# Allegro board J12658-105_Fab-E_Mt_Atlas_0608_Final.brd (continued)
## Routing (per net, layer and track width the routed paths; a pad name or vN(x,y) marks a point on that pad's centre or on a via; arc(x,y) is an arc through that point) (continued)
VDD_HDR_EN: length 2.4
  TOP w0.127: v1(60.96,69.22) 60.67,69.5 U2.4
  BOTTOM w0.127: v1(60.96,69.22) 60.58,69.22 60.2,69.6 R131.2
VDD_HDR_FB: length 3.6
  TOP w0.127: R130.1 R132.2 R133.1 57.62,69.04 U2.3
VDD_IMU: length 15.1
  TOP w0.254: v1(28.59,49.64) 28.18,50.05 U14.8 ; U14.5 26.11,49.28 v1(25.59,48.77) ; R24.1 v1(22.29,51.82) 21.97,51.5 C14.1 21.46,51.43 FB6.2 ; R28.1 v1(22.29,50.8) 22.1,50.61 C15.1
  BOTTOM w0.508: v1(28.59,49.64) 26.47,49.64 v1(25.59,48.77) 24.32,48.77 v1(22.29,50.8) v1(22.29,51.82)
VDD_USB: length 40.4
  TOP w0.254: v1(16.32,61.4) U7.A1
  TOP w0.305: C8.1 17.08,60.64 v1(16.32,61.4)
  L3_SIG w0.508: v1(42.35,46.99) 42.35,48.52 38.17,52.71 38.17,60.17 v1(36.85,61.49)
  L4_SIG w0.381: v1(36.85,61.49) 36.63,61.49 36.04,62.08 25.5,62.08 25.32,61.9 18.08,61.9 18.06,61.93 16.84,61.93 v1(16.32,61.4)
  BOTTOM w0.381: R273.1 v1(42.35,46.99)
VDD_USB_EN: length 2.6
  TOP w0.254: U7.B2 18.1,63.18 C5.1
  TOP w0.508: R10.2 C5.1
VDD_USB_R: length 2.6
  BOTTOM w0.381: R273.2 C98.1 41.47,44.64 v1(41.41,44.58) 41.34,44.64 R33.1
15_4_GPIO0: length 8.1
  TOP w0.127: R97.1 v1(38.42,23.3) ; U29.10 40.95,18.28 v1(40.77,18.1)
  L3_SIG w0.127: v1(38.42,23.3) 38.42,21.97 39.94,20.45 39.94,18.92 v1(40.77,18.1)
15_4_GPIO1: length 7.9
  TOP w0.127: U29.9 41.04,18.78 v1(40.77,19.05) ; R83.2 R84.2 39.43,23.3 39.31,23.18 v1(39.31,22.23)
  L3_SIG w0.127: v1(39.31,22.23) 40.77,20.76 v1(40.77,19.05)
15_4_GPIO2: length 3.7
  TOP w0.127: R98.2 R99.2 41.72,21.02 42.48,21.02 42.82,20.68 U29.7
15_4_GPIO3: length 5.1
  TOP w0.127: R85.2 41.53,23.5 41.53,22.23 R100.2 42.61,21.72 43.32,21 U29.6
15_4_GPIO4: length 4.5
  TOP w0.127: R86.2 43.05,22.03 43.43,21.65 R101.2 43.82,21.53 U29.5
15_4_GPIO5: length 4.1
  TOP w0.127: R87.1 44.51,23.56 44.51,21.34 44.32,21.15 U29.4
15_4_RESET_N: length 67.4
  TOP w0.127: R108.1 v1(50.16,17.78)
  L3_SIG w0.127: v1(60.89,50.67) 60.89,50.32 60.63,50.06 60.63,48.82 61.27,48.18 61.27,33.46 60.69,32.88 60.69,31.26 60.77,31.18 60.77,17.88 v1(60.08,17.19)
  L4_SIG w0.127: v1(64.64,68.58) 64.33,68.26 64.33,66.55 61.53,63.75 61.53,51.31 v1(60.89,50.67) ; v1(60.08,17.19) 59.99,17.19 59.48,16.68 57.27,16.68 56.91,17.04 53.42,17.04 52.99,16.61 51.33,16.61 v1(50.16,17.78)
  BOTTOM w0.127: v1(64.64,68.58) 64.83,68.39 65.47,68.39 65.61,68.53 U32.3
15_4_RESET_N_R: length 1.8
  TOP w0.127: U29.25 R108.2
15_4_XIN: length 5.1
  TOP w0.127: C40.1 39.75,14.2 39.54,14.42 Y4.3 39.93,15 40.23,15 40.83,15.61 40.83,16.57 41.04,16.78 U29.13
15_4_XOUT: length 5.1
  TOP w0.127: U29.12 41.16,17.28 40.64,16.76 39.12,16.76 38.44,16.09 Y4.1 38.32,16.13 C37.1
A_3P3V: length 2.4
  TOP w0.508: FB10.2 10.29,33.15 10.16,33.02
A_5P0V: length 2.4
  TOP w0.508: 10.16,30.48 FB12.2
A_VIN: length 2.3
  TOP w0.508: FB13.2 10.16,22.86
ADC_AGND: length 1.5
  TOP w0.254: U22.L10 v1(37.38,43.57)
  BOTTOM w0.381: v1(37.38,43.57) 37.64,43.31 R192.1
AMBIENT_INT_N: length 2.2
  TOP w0.127: U10.4 19.79,56.52 v1(19.67,56.52)
  BOTTOM w0.127: v1(19.67,56.52) 20.32,55.87 R150.2
AP_COMP_AREF: length 13.5
  TOP w0.127: U22.H9 v1(34.98,42.77)
  BOTTOM w0.127: R170.2 R169.2 39.12,46.67 38.93,46.86 38.93,48.83 38.67,49.09 C75.1 R171.1 37.21,48.2 36.19,47.18 36.19,43.42 35.93,43.16 35.38,43.16 v1(34.98,42.77)
AP_GPIO0_ADC0_SPI_S_CS_N: length 73.4
  TOP w0.127: v1(30.99,45.3) 31.38,44.91 U22.D12
  L3_SIG w0.127: v1(7.75,46.48) 7.25,45.99 7.25,37.13 8.12,36.26 8.12,35.16 8.02,35.06 8.02,26.05 7.75,25.78 7.75,25.67 7.74,25.66 7.74,12.95 7.75,12.94 7.75,12.24 9.14,10.85 9.14,9.58 9.65,9.07 13.85,9.07 v1(14.67,8.25)
  L4_SIG w0.127: v1(30.99,45.3) 30.99,45.34 29.91,46.42 24.42,46.42 23.58,45.58 21.12,45.58 20.33,46.37 19.84,46.37 19.49,46.01 19.49,45.7 19.14,45.35 17.94,45.35 17.81,45.22 9,45.22 v1(7.75,46.48)
  BOTTOM w0.127: R178.2 29.46,46.61 29.84,46.23 30.06,46.23 v1(30.99,45.3) ; R258.2 v1(14.67,8.25)
AP_GPIO0_ADC0_SPI_S_CS_N_R_HDR: length 9.8
  BOTTOM w0.203: R258.1 12.38,8.25 11.75,7.62 11.75,6.86 11.05,6.16 9.21,6.16 8.13,5.08 5.08,5.08
AP_GPIO1_ADC1_SPI_S_MISO: length 111.7
  TOP w0.127: U28.13 26.11,21.66 v1(24.96,20.51) ; U22.E10 v1(31.78,43.57)
  L3_SIG w0.127: v1(11.18,43.05) 11.85,42.37 11.85,41.49 11.75,41.39 11.75,38.77 11.85,38.67 11.85,38.42 11.9,38.37 11.9,37.44 11.91,37.43 11.91,37.04 11.91,36.67 11.91,36.67 11.91,36.63 12.08,36.47 12.08,16.12 v1(14.61,13.59) ; v1(27.05,31.81) 27.05,30.71 24.93,28.59 24.53,28.59 23.23,27.28 23.23,25.35 24,24.57 24,22.86 24.96,21.91 v1(24.96,20.51)
  L4_SIG w0.127: v1(11.18,43.05) 12.44,43.05 13.4,44.01 17.01,44.01 17.69,43.32 18.88,43.32 19.18,43.02 21.05,43.02 21.34,43.31 21.46,43.31 22.03,43.88 27.24,43.88 27.95,43.17 31.26,43.17 31.65,43.57 v1(31.78,43.57) ; v1(41.71,34.06) 41.55,33.91 40.46,33.91 39.34,32.79 30.96,32.79 30.39,33.36 27.72,33.36 27.05,32.69 27.05,32.36 27.05,32.36 v1(27.05,31.81) ; v1(24.96,20.51) 18.86,20.51 18.66,20.31 17.92,20.31 17.27,20.96 16.19,20.96 15.94,20.7 14.29,20.7 13.91,20.32 13.91,14.29 v1(14.61,13.59)
  BOTTOM w0.127: R213.2 40.83,38.16 40.83,35.57 41.71,34.69 v1(41.71,34.06) ; R242.2 v1(14.61,13.59)
AP_GPIO1_ADC1_SPI_S_MISO_HDR: length 9.6
  BOTTOM w0.203: J15.38 7.56,10.16 8.81,11.42 10.66,11.42 12.3,13.06 12.3,13.44 12.45,13.59 R242.1
AP_GPIO2_ADC2_SPI_S_SCK: length 51.7
  TOP w0.127: U22.E11 v1(31.78,44.37)
  L3_SIG w0.127: v1(14.61,16.26) 12.53,18.33 12.53,36.66 12.37,36.82 12.37,36.85 12.37,37.62 12.36,37.63 12.36,38.56 12.36,38.56 12.31,38.61 12.31,38.86 12.2,38.96 12.2,41.2 12.31,41.3 12.31,43.95 v1(12.19,44.07)
  L4_SIG w0.127: v1(31.78,44.37) 31.38,44.77 30.82,44.77 30.59,45 30.59,45.32 29.72,46.19 24.51,46.19 23.67,45.35 20.42,45.35 19.86,44.79 19.53,44.79 19.07,44.34 18.17,44.34 17.93,44.58 12.7,44.58 v1(12.19,44.07)
  BOTTOM w0.127: R236.2 v1(14.61,16.26)
AP_GPIO2_ADC2_SPI_S_SCK_HDR: length 9.5
  BOTTOM w0.203: R236.1 12.49,16.26 10.26,14.03 9.58,14.03 8.25,12.7 J15.36
AP_GPIO3_ADC3_SPI_S_MOSI: length 63.5
  TOP w0.127: U22.E12 v1(31.78,45.17)
  L3_SIG w0.127: v1(10.16,45.85) 10.16,43.94 8.81,42.6 8.81,37.54 8.81,37.33 9.27,36.88 9.27,35.03 9.27,34.84 9.26,34.83 9.26,34.68 9.16,34.59 9.16,26.87 9.44,26.59 10.86,26.59 11.16,26.29 11.16,13.56 13.8,10.92 v1(14.61,10.92)
  L4_SIG w0.127: v1(31.78,45.17) 30.53,46.42 30.3,46.65 24.32,46.65 24.04,46.37 20.65,46.37 20.42,46.6 19.74,46.6 19.26,46.11 19.26,46 18.83,45.58 12.36,45.58 12.09,45.85 v1(10.16,45.85)
  BOTTOM w0.127: R251.2 v1(14.61,10.92)
AP_GPIO3_ADC3_SPI_S_MOSI_HDR: length 9.4
  BOTTOM w0.203: R251.1 12.76,10.6 12.45,10.6 10.73,8.89 9.78,8.89 8.51,7.62 J15.40
AP_GPIO4_ADC4: length 72.8
  TOP w0.127: v1(38.42,25.65) R83.1 ; 54.9,46.13 54.99,46.23 R38.1 ; 54.9,46.13 v1(54.86,46.13) ; 54.9,46.13 54.15,45.38 54.15,43.93 53.55,43.33 53.55,42.25 53.09,41.79 v1(53.09,41.27) ; U22.F9 v1(32.58,42.77)
  L3_SIG w0.127: v1(54.86,46.13) 55.66,46.13 56.31,45.48 56.31,39.57 56.44,39.44 56.44,25.14 v1(57.19,24.39)
  L4_SIG w0.127: v1(57.19,24.39) 54.22,24.39 53.4,25.21 42.72,25.21 42.13,25.8 40.49,25.8 39.95,25.26 38.81,25.26 v1(38.42,25.65) ; v1(32.58,42.77) 32.98,43.16 34.35,43.16 34.58,42.93 34.58,42.62 34.83,42.36 36.75,42.36 36.99,42.12 36.99,41.8 37.22,41.57 39.28,41.57 40.2,40.65 52.46,40.65 v1(53.09,41.27)
AP_GPIO4_ADC4_HDR: length 8
  TOP w0.203: J14.13 61.34,48.26 59.31,46.23 R38.2
AP_GPIO5_ADC5: length 73.2
  TOP w0.127: v1(54.74,43.18) R44.1 ; v1(32.58,43.57) 32.98,43.17 U22.F10 ; R98.1 v1(40.01,23.37)
  L3_SIG w0.127: v1(60.25,29.06) 60.55,29.35 60.55,31.09 60.46,31.17 60.46,32.98 60.63,33.14 60.9,33.41 60.9,37.64 60.93,37.68 60.93,42.88 v1(60.63,43.18) ; v1(40.01,23.37) v1(40.01,28.6)
  L4_SIG w0.127: v1(60.25,29.06) 59.75,28.56 52.01,28.56 51.75,28.31 50.89,28.31 50.13,29.07 45.47,29.07 45.34,29.2 42.53,29.2 41.89,28.56 40.65,28.56 40.61,28.6 v1(40.01,28.6) ; v1(32.58,43.57) 32.98,43.96 34.35,43.96 34.59,43.72 34.59,43.4 34.82,43.17 38.72,43.17 39.78,44.23 40.72,44.23 41.04,43.92 44.92,43.92 45.16,43.68 49.07,43.68 49.28,43.88 49.72,43.88 50.81,42.79 54.34,42.79 v1(54.74,43.18) v1(60.63,43.18)
AP_GPIO5_ADC5_HDR: length 8.2
  TOP w0.203: J14.15 61.28,45.72 59.18,43.62 57.59,43.62 57.15,43.18 R44.2
AP_GPIO6_ADC6: length 15
  TOP w0.127: v1(33.71,31.06) 33.18,31.59 U38.4 ; U22.L9 v1(37.38,42.77)
  L3_SIG w0.127: v1(33.71,31.06) 33.84,31.2 33.84,34.62 34.24,35.02 34.24,35.38 35.62,36.76 35.93,36.76 36.18,37.01 36.18,40.69 36.98,41.49 36.98,42.36 v1(37.38,42.77)
AP_GPIO6_ADC6_HDR: length 8
  TOP w0.203: R47.2 61.47,41.15 J14.17
AP_GPIO6_ADC6_MUX: length 54
  TOP w0.127: v1(54.67,41.85) 54.67,41.5 55.03,41.15 R47.1 ; U38.1 31,32.89 31.37,32.52 31.37,31.62 v1(31.94,31.05) ; v1(41.76,25.41) 41.25,24.89 R85.1
  L3_SIG w0.127: v1(54.74,23.88) 55.36,24.5 55.36,35.14 54.99,35.51 54.54,35.51 54.26,35.79 54.26,36.4 55.23,37.38 55.23,40.9 54.67,41.46 v1(54.67,41.85) ; v1(31.86,26.04) 31.86,29.52 32.09,29.74 32.09,30.9 v1(31.94,31.05)
  L4_SIG w0.127: v1(31.86,26.04) 32.36,26.53 34.59,26.53 36.09,25.03 40.05,25.03 40.42,25.41 v1(41.76,25.41) 42.21,24.96 53.02,24.96 54.1,23.88 v1(54.74,23.88)
AP_GPIO7_ADC7: length 76.3
  TOP w0.127: R261.1 v1(57.66,2.54) ; U22.K8 v1(36.58,41.97)
  L3_SIG w0.127: v1(57.66,2.54) 57.36,2.84 57.36,23.01 57.47,23.11 57.47,23.7 58.06,24.3 58.06,24.89 57.92,25.02 57.08,25.86 57.08,37.47 57.71,38.09 57.71,38.5 56.54,39.67 56.54,46.51 56.67,46.64 56.67,49 v1(56.52,49.15)
  L4_SIG w0.127: v1(56.52,49.15) 56.06,48.69 53.62,48.69 53.34,48.41 47.85,48.41 47.2,47.76 44.04,47.76 43.22,48.59 41.61,48.59 v1(41.27,48.26)
  BOTTOM w0.127: v1(41.27,48.26) 40.96,47.94 40.96,46.29 40.78,46.12 40.46,46.12 39.69,45.34 R33.2 39.31,44.64 38.64,43.97 37.23,43.97 36.98,43.72 36.98,42.36 v1(36.58,41.97) 36.64,41.91 R199.1
AP_GPIO7_ADC7_HDR: length 5
  TOP w0.203: 63.5,5.08 60.96,2.54 R261.2
AP_GPIO8_SPI1_M_SCK: length 78.7
  TOP w0.127: U22.D6 31.38,39.97 v1(30.98,39.57) ; R96.1 49.91,22.23 v1(50.23,21.91) ; R63.2 v1(13.91,34.42)
  L3_SIG w0.127: v1(14.49,37.8) 14.69,37.6 14.69,35.84 14.64,35.79 14.64,35.15 v1(13.91,34.42) 13.91,30.28 14.48,29.71 14.48,27.91 14.28,27.71 13.64,27.71 13.45,27.52 13.45,26.81 13.62,26.64 13.99,26.64 14.33,26.31 14.33,23.02 v1(13.84,22.54)
  L4_SIG w0.127: v1(13.84,22.54) 14.14,22.84 23.52,22.84 23.75,22.61 32.31,22.61 v1(33.36,21.55) 33.62,21.81 38.76,21.81 39.12,21.45 44.94,21.45 45.08,21.58 45.59,22.1 50.04,22.1 v1(50.23,21.91) ; v1(14.49,37.8) 14.93,38.24 23.17,38.24 23.69,37.72 24.57,37.72 25.4,38.56 26.34,38.56 26.63,38.85 29.55,38.85 29.86,39.16 30.58,39.16 v1(30.98,39.57)
  BOTTOM w0.127: R229.2 31.88,19.16 32.55,19.84 32.91,19.84 33.36,20.29 v1(33.36,21.55)
AP_GPIO8_SPI1_M_SCK_BLE: length 2.7
  TOP w0.127: U30.12 31.71,16.22 31.88,16.38 v1(31.88,17.14)
  BOTTOM w0.127: R229.1 v1(31.88,17.14)
AP_GPIO8_SPI1_M_SCK_HDR: length 7.9
  TOP w0.203: J15.20 6.57,34.51 10.92,34.51 11.01,34.42 R63.1
AP_GPIO8_SPI1_M_SCK_R: length 4.3
  TOP w0.127: R96.2 48.13,22.23 47.62,21.72 47.62,19.56 47.35,19.28 U29.28
AP_GPIO9_SPI1_M_MISO: length 78.4
  TOP w0.127: v1(29.38,39.57) 29.78,39.97 U22.B6 ; R73.2 v1(13.84,29.21) ; R92.1 v1(49.15,25.65)
  L3_SIG w0.127: v1(47.12,20.37) 48.77,22.02 48.77,25.27 v1(49.15,25.65) ; v1(21.27,29.66) 21.02,29.42 21.02,28.02 20.69,27.69 20.69,22.39 v1(21.32,21.76) ; v1(13.84,29.21) 13.51,29.54 13.51,34.58 13.94,35.01 14,35.01 14.41,35.43 14.41,35.88 14.47,35.93 14.47,36.93 v1(13.91,37.48)
  L4_SIG w0.127: v1(29.38,39.57) 28.89,39.08 26.54,39.08 26.24,38.79 22.11,38.79 21.8,38.47 14.6,38.47 13.91,37.78 v1(13.91,37.48) ; v1(13.84,29.21) 14.49,29.86 21.07,29.86 v1(21.27,29.66) ; v1(21.32,21.76) 22.78,21.76 23.58,20.97 24.52,20.97 25.39,21.84 28.24,21.84 29.25,20.83 30.52,20.83 31.17,20.18 32.02,20.18 v1(32.77,19.43) 32.96,19.62 33.88,19.62 33.88,19.63 38.51,19.63 39.26,20.37 v1(47.12,20.37)
  BOTTOM w0.127: v1(32.77,19.43) R228.2
AP_GPIO9_SPI1_M_MISO_BLE: length 3.8
  TOP w0.127: U30.11 31.65,15.52 32.77,16.64 v1(32.77,17.14)
  BOTTOM w0.127: R228.1 v1(32.77,17.14)
AP_GPIO9_SPI1_M_MISO_HDR: length 7.8
  TOP w0.203: R73.1 11.62,29.21 11.37,29.46 6.1,29.46 J15.22
AP_GPIO9_SPI1_M_MISO_R: length 6.4
  TOP w0.127: U29.1 45.82,20.87 45.97,21.02 46.99,21.02 47.28,21.3 47.28,22.32 48.13,23.18 R91.1 R92.2
AP_GPIO10_SPI1_M_MOSI: length 77.6
  TOP w0.127: v1(28.58,39.57) 28.98,39.97 U22.A6 ; R90.1 v1(47.12,25.65) ; R77.2 v1(13.84,27.18)
  L3_SIG w0.127: v1(47.12,25.65) 47.12,21.91 v1(46.8,21.59) ; v1(15.75,21.15) 15.62,21.27 15.62,25.4 v1(13.84,27.18) 14.06,27.18 14.7,27.82 14.7,30.37 14.34,30.73 14.34,33.31 14.94,33.91 15.29,33.91 15.63,34.25 15.63,34.66 15.1,35.19 15.1,35.6 15.15,35.65 15.15,38.03 14.86,38.32 14.86,38.87 v1(14.65,39.08)
  L4_SIG w0.127: v1(46.8,21.59) 45.4,21.59 45.3,21.49 45.3,21.49 45.04,21.22 39.03,21.22 38.67,21.58 34.79,21.58 v1(34.42,21.21) 34.02,20.82 31.83,20.82 31.62,21.02 31.16,21.02 30.11,22.06 25.49,22.06 25.3,22.06 24.43,21.2 23.67,21.2 22.71,22.16 16.76,22.16 v1(15.75,21.15) ; v1(14.65,39.08) 14.95,39.38 19.74,39.38 20.35,38.77 21.77,38.77 22.16,39.15 25.09,39.15 25.58,39.64 26.2,39.64 26.27,39.57 v1(28.58,39.57)
  BOTTOM w0.127: R245.2 33.59,19.48 34.42,20.3 v1(34.42,21.21)
AP_GPIO10_SPI1_M_MOSI_BLE: length 9.3
  TOP w0.127: U30.8 31.79,13.42 32.13,13.08 32.13,12.45 v1(32.64,11.94)
  BOTTOM w0.127: R245.1 33.59,12.89 v1(32.64,11.94)
AP_GPIO10_SPI1_M_MOSI_HDR: length 7.7
  TOP w0.203: J15.24 6.03,26.99 11.11,26.99 11.3,27.18 R77.1
AP_GPIO10_SPI1_M_MOSI_R: length 4.6
  TOP w0.127: R90.2 47.12,22.8 45.32,21 U29.2
AP_GPIO11_SPI1_M_CS0_N: length 93.9
  TOP w0.127: U22.C6 30.58,39.97 v1(30.18,39.57) ; R81.2 v1(13.84,25.15) ; R89.1 v1(46.1,25.65)
  L3_SIG w0.127: v1(8.64,25.27) 8.8,25.44 8.8,26.58 8.7,26.68 8.7,34.78 8.8,34.87 8.8,36.66 8.33,37.13 8.33,41.9 v1(8,42.23) ; v1(46.09,23.31) 46.1,23.32 v1(46.1,25.65)
  L4_SIG w0.127: v1(30.18,39.57) 29.79,39.96 27.82,39.96 27.73,39.87 25.34,39.87 24.96,39.48 22.77,39.48 21.98,40.27 21.34,40.27 21.11,40.5 14.81,40.5 14.24,41.07 11.19,41.07 10.61,41.65 8.58,41.65 v1(8,42.23) ; v1(46.09,23.31) 45.51,23.31 45.04,22.85 41.94,22.85 41.5,23.28 41.5,23.38 41.18,23.7 40.86,23.7 40.4,23.24 40.4,23.2 40.17,22.97 39.84,22.97 39.61,23.2 38.87,23.2 38.52,22.85 34.75,22.85 33.83,23.76 27.18,23.76 25.94,25 24.16,25 23.83,25.34 22.08,25.34 22.07,25.35 21.74,25.35 20.91,24.51 19.1,24.51 18.13,25.48 17.81,25.48 17.58,25.25 17.58,24.88 17.45,24.75 14.24,24.75 v1(13.84,25.15) 12.39,26.6 9.42,26.6 8.64,25.82 v1(8.64,25.27)
  BOTTOM w0.127: R211.2 29.02,34.65 29.79,35.42 29.79,39.17 v1(30.18,39.57)
AP_GPIO11_SPI1_M_CS0_N_HDR: length 7.9
  TOP w0.203: R81.1 11.68,25.15 11.01,24.47 8.29,24.47 7.37,25.4 J15.26
AP_GPIO11_SPI1_M_CS0_N_R: length 4.9
  TOP w0.127: R89.2 R88.2 45.09,22.23 44.82,21.96 U29.3
AP_GPIO12_SPI1_M_CS1_N: length 55.7
  TOP w0.127: U22.B5 29.35,38.73 27.28,38.73 v1(26.8,38.25) ; R263.1 v1(16.28,11.49)
  L3_SIG w0.127: v1(22.23,27.05) 22.23,27.27 22.52,27.56 22.52,27.84 24.3,29.61 24.3,31.1 26.04,32.84 26.04,34.11 25.57,34.58 25.57,37.24 25.81,37.48 26.02,37.48 v1(26.8,38.25) ; v1(17.14,25.15) 17.14,24.32 17.01,24.18 17.01,20.19 16.13,19.31 16.13,18.38 15.52,17.78 15.52,12.25 v1(16.28,11.49)
  L4_SIG w0.127: v1(29.21,11.05) 28.37,11.89 16.67,11.89 v1(16.28,11.49) ; v1(17.14,25.15) 19.05,27.05 v1(22.23,27.05)
  BOTTOM w0.127: R250.2 v1(29.21,11.05) ; R216.2 v1(17.14,25.15) ; v1(26.8,38.25) 26.9,38.25 R205.2
AP_GPIO12_SPI1_M_CS1_N_BLE: length 3.9
  TOP w0.127: v1(32.64,11.05) 31.88,11.81 31.88,12.57 31.73,12.72 U30.7
  BOTTOM w0.127: R250.1 v1(32.64,11.05)
AP_GPIO12_SPI1_M_CS1_N_HDR: length 11
  BOTTOM w0.203: R216.1 14.61,24.64 13.43,24.64 12.92,24.13 9.65,24.13 8.38,22.86 J15.28
AP_GPIO13_SPI1_M_CS2_N: length 47.8
  TOP w0.127: v1(32.95,34.23) 27.67,34.23 26.54,35.36 26.54,37.28 v1(25.75,38.08) 26.84,39.17 U22.A5
  L3_SIG w0.127: v1(32.95,34.23) 32.54,33.82 32.54,33.43 32.54,33.42 32.54,33.37 32.77,33.14 32.79,33.14 32.8,33.13 32.8,30.29 32.79,30.28 32.79,29.96 32.8,29.95 32.8,25.14 32.51,24.84 32.51,20.57 31.83,19.89 v1(31.83,19.75)
  L4_SIG w0.127: v1(18.16,20.76) 18.19,20.74 24.62,20.74 25.42,21.54 28.21,21.54 29.25,20.5 30.44,20.5 31.19,19.75 v1(31.83,19.75)
  BOTTOM w0.127: R214.1 34.73,34.09 34.59,34.23 v1(32.95,34.23) ; R206.2 26.12,38.08 v1(25.75,38.08) ; 18.16,21.59 v1(18.16,20.76)
AP_GPIO13_SPI1_M_CS2_N_HDR: length 13.1
  BOTTOM w0.203: R219.1 17.14,21.59 16.66,22.07 11.72,22.07 10.78,21.13 8.36,21.13 7.56,20.32 J15.30
AP_GPIO14_SPI1_M_CS3_N: length 94.7
  TOP w0.127: v1(30.98,38.77) 31.38,39.17 U22.D5
  L3_SIG w0.127: v1(24.26,19.18) 25.35,20.27 25.35,22.14 24.24,23.25 24.24,24.85 23.46,25.63 23.46,27.19 24.63,28.36 25.02,28.36 27.65,30.98 27.65,31.2 27.83,31.38 27.83,32.74 27.06,33.51 27.06,35.75 27.04,35.78 27.04,36.11 27.96,37.03 27.96,37.44 28.19,37.67 28.19,38.13 28.42,38.36 30.58,38.36 v1(30.98,38.77) 31.23,38.77 31.62,39.17 31.99,39.17 32.18,39.35 32.18,39.73 31.39,40.52 31.39,41.32 31.14,41.57 30.83,41.57 30.58,41.81 30.58,42.12 30.34,42.37 28.82,42.37 26.61,44.58 26.61,45.51 25.09,47.02 24.69,47.02 23.88,47.83 23.88,50.93 23.73,51.09 23.73,52.8 25.42,54.49 25.42,62.59 v1(26.2,63.37)
  L4_SIG w0.127: v1(14.67,20.26) 15.37,19.56 15.75,19.56 16.38,18.92 19.81,18.92 20.32,18.41 23.5,18.41 v1(24.26,19.18) ; v1(26.2,63.37) 27.84,63.37 29.62,65.15 39.87,65.15 v1(40.83,66.1)
  BOTTOM w0.127: v1(14.67,20.26) 14.22,20.7 R222.2 ; C104.1 v1(40.83,66.1) 40.83,66.11 40.83,67.73 40.83,67.74 40.83,68.83 41.08,69.09 R135.2 ; v1(30.98,38.77) 30.59,38.37 30.59,34.72 R210.2
AP_GPIO14_SPI1_M_CS3_N_HDR: length 9.7
  BOTTOM w0.203: R222.1 11.94,20.7 10.99,19.75 8.95,19.75 8.06,18.86 8.06,18.1 7.75,17.78 J15.32
AP_GPIO15_I2S_RXD: length 46.9
  TOP w0.127: U22.C5 30.58,39.17 v1(30.18,38.77) ; U25.3 32.85,30.06 32.96,30.16 33.15,30.16 33.19,30.12 v1(33.19,30.12) ; v1(54.74,33.02) R67.2
  L3_SIG w0.127: v1(25.79,30.14) 25.79,31.11 26.82,32.14 26.82,35.68 26.81,35.68 26.81,36.21 27.13,36.52 27.13,36.93 27.96,37.76 27.96,38.23 28.5,38.77 v1(30.18,38.77)
  L4_SIG w0.127: v1(54.74,33.02) 54.34,32.63 51.14,32.63 50.06,33.71 48.81,33.71 48.18,33.08 46.04,33.08 45.9,32.94 40.78,32.94 39.89,32.05 33.58,32.05 33.19,31.67 33.19,30.12 ; 33.19,30.12 33.15,30.16 32.51,30.16 32.07,30.61 31.53,30.61 30.88,29.96 25.97,29.96 v1(25.79,30.14) ; 33.19,30.12 v1(33.19,30.12)
AP_GPIO15_I2S_RXD_HDR: length 12.6
  TOP w0.203: J14.28 64.77,31.75 64.77,33.4 64.08,34.09 62.6,34.09 61.59,33.08 56.45,33.08 R67.1
AP_GPIO16_I2S_RSCK: length 52.9
  TOP w0.127: U22.B4 29.78,38.37 v1(29.38,37.97) ; R80.2 54.74,26.67 v1(54.74,26.92) ; v1(24.75,26.67) 26.1,26.67 26.76,27.32 U28.3
  L3_SIG w0.127: v1(29.38,37.97) 28.99,37.57 28.99,34.78 28.75,34.55 28.75,30.67 26.44,28.36 25.97,28.36 25.51,27.9 25.18,27.9 24.75,27.47 v1(24.75,26.67)
  L4_SIG w0.127: v1(54.74,26.92) 54.1,27.56 54.1,28.07 53.83,28.33 52.1,28.33 51.85,28.08 50.79,28.08 50.03,28.84 45.38,28.84 45.25,28.97 42.62,28.97 41.86,28.21 39.84,28.21 38.89,29.16 34.92,29.16 34.68,28.92 26.2,28.92 24.75,27.47 v1(24.75,26.67)
AP_GPIO16_I2S_RSCK_HDR: length 10.8
  TOP w0.203: J14.30 64.75,26.65 62.79,26.65 61.69,25.55 56.75,25.55 R80.1
AP_GPIO17_I2S_RWS: length 44.3
  TOP w0.127: v1(30.23,25.91) 30.84,26.52 30.84,27.53 30.9,27.6 U25.6 ; v1(30.98,37.97) 31.38,38.37 U22.D4 ; v1(54.74,24.89) 54.74,24.64 R94.2
  L3_SIG w0.127: v1(30.98,37.97) 31.38,37.57 31.38,37.01 31.63,36.77 31.95,36.77 32.18,36.53 32.18,35.36 31.52,34.7 31.52,30.55 31.34,30.37 31.34,30.33 30.77,29.76 30.77,26.46 v1(30.23,25.91)
  L4_SIG w0.127: v1(30.23,25.91) 30.66,26.34 31.52,26.34 32.01,26.83 34.62,26.83 35.35,26.1 51.67,26.1 51.69,26.07 53.12,26.07 54.3,24.89 v1(54.74,24.89)
AP_GPIO17_I2S_RWS_HDR: length 10.3
  TOP w0.203: J14.32 64.77,24.13 61.59,24.13 61.34,23.88 R94.1
AP_GPIO18_I2S_TSCK: length 51.3
  TOP w0.127: U22.A4 28.98,38.37 v1(28.58,37.97) ; U28.6 24.81,27.6 24.74,27.53 24.74,27.27 24.13,26.66 v1(24.13,25.91)
  L3_SIG w0.127: v1(24.13,25.91) 24.13,26.7 24.52,27.09 24.52,27.56 25.09,28.13 25.42,28.13 25.88,28.59 26.36,28.59 28.52,30.76 28.52,33.22 28.19,33.55 28.19,37.35 28.58,37.74 v1(28.58,37.97)
  L4_SIG w0.127: v1(24.13,25.91) 24.52,25.51 25.34,25.51 26.13,26.3 27.34,26.3 27.65,26 27.65,25.9 28.08,25.46 29.64,25.46 29.91,25.2 31.49,25.2 31.51,25.19 32.22,25.19 32.23,25.2 33.73,25.2 33.87,25.06 35.1,25.06 35.81,24.35 40.33,24.35 40.37,24.38 41.81,24.38 41.93,24.27 51.85,24.27 53.21,22.91 v1(53.21,22.86)
  BOTTOM w0.127: R218.2 54.04,22.1 53.27,22.86 v1(53.21,22.86)
AP_GPIO18_I2S_TSCK_HDR: length 11.2
  BOTTOM w0.203: 66.04,22.86 64.9,21.72 62.57,21.72 62.56,21.73 57.58,21.73 57.21,22.1 R218.1
AP_GPIO19_I2S_TWS: length 61.9
  TOP w0.127: U22.C4 30.58,38.37 v1(30.18,37.97) ; v1(21.91,24.96) 23.69,24.96 24.16,24.49 U28.10
  L3_SIG w0.127: v1(21.91,24.96) 21.6,25.26 21.6,27.31 22.06,27.77 22.06,28.03 22.68,28.65 22.68,30.74 23.84,31.89 23.84,36.41 v1(24.26,36.83)
  L4_SIG w0.127: v1(53.79,19.51) 54.09,19.51 54.55,19.96 54.55,20.6 53.74,21.4 51.15,21.4 50.88,21.67 50.88,21.95 50.88,22.14 50.87,22.15 50.86,22.15 50.85,22.16 50.85,22.17 50.49,22.53 50.48,22.53 50.44,22.58 45.42,22.58 45.23,22.39 39.78,22.39 39.42,22.74 39.06,22.74 38.71,22.39 34.56,22.39 33.74,23.21 25.43,23.21 23.69,24.96 v1(21.91,24.96) ; v1(30.18,37.97) 29.79,38.36 27.82,38.36 27.17,37.71 25.93,37.71 25.06,36.83 v1(24.26,36.83)
  BOTTOM w0.127: v1(53.79,19.51) 53.8,19.49 R224.2
AP_GPIO19_I2S_TWS_HDR: length 11.2
  BOTTOM w0.203: 66.04,20.32 64.85,19.13 63.11,19.13 62.93,19.3 57.66,19.3 57.43,19.53 55.54,19.53 R224.1
AP_GPIO20_I2S_TXD: length 55
  TOP w0.127: v1(29.39,37.17) 29.78,37.57 U22.B3 ; U25.10 30.25,24.49 v1(30.23,24.51)
  L3_SIG w0.127: v1(30.23,24.51) 30.23,17.91 v1(30.99,17.14) ; v1(29.39,37.17) 29.78,36.78 29.78,33.3 29.97,33.11 29.97,30.9 26.64,27.56 26.64,26.86 26.16,26.39 v1(26.16,25.78)
  L4_SIG w0.127: v1(30.99,17.14) 31.48,16.65 33.42,16.65 34.25,17.49 34.9,17.49 35.17,17.76 37.42,17.76 37.78,17.4 37.78,16.64 39.13,15.29 48.84,15.29 48.97,15.16 53.07,15.16 v1(53.53,15.62) ; v1(30.23,24.51) 29.84,24.51 29.4,24.96 26.99,24.96 v1(26.16,25.78)
  BOTTOM w0.114: R233.2 54.13,17.4 53.53,16.8 v1(53.53,15.62)
AP_GPIO20_I2S_TXD_HDR: length 11.3
  BOTTOM w0.203: 66.04,17.78 64.9,16.64 57.79,16.64 57.02,17.4 R233.1
AP_GPIO21_SPI0_M_SCK: length 46.3
  TOP w0.127: U22.A3 28.98,37.57 v1(28.59,37.17) ; v1(10.1,52.93) 9.49,52.93 R20.2 ; U23.13 22.16,33.73 21.71,33.27 21.08,33.27 19.98,34.37 v1(19.98,34.81) ; U15.6 v1(19.18,49.98)
  L3_SIG w0.127: v1(19.98,34.81) 19.83,34.96 19.83,36.14 20.07,36.37 v1(20.07,36.83) 20.07,38.28 20.04,38.31 20.04,38.78 20,38.82 20,39.6 19.98,39.62 19.68,39.92 19.68,42.73 20.26,43.31 20.26,43.82 20.26,43.82 20.26,44.77 19.61,45.42 19.61,47.17 20.11,47.67 20.11,48.11 20.2,48.2 20.2,48.56 19.18,49.58 v1(19.18,49.98)
  L4_SIG w0.127: v1(28.59,37.17) 26.62,37.17 25.88,36.44 23.81,36.44 23.42,36.83 v1(20.07,36.83) ; v1(19.18,49.98) 18.43,50.72 16.26,50.72 14.86,49.33 14.26,49.33 13.99,49.59 9.78,49.59 9.35,50.03 9.35,52.21 10.1,52.96 v1(10.1,52.93)
AP_GPIO21_SPI0_M_SCK_HDR: length 3.5
  TOP w0.203: R20.1 8.19,53.34 J15.4
AP_GPIO22_SPI0_M_MISO: length 50.2
  TOP w0.127: U22.C3 30.58,37.57 v1(30.18,37.17) ; U15.2 v1(14.6,50.48) ; v1(20.46,31.59) 21.3,31.59 21.49,31.78 U23.10 24.05,31.78 24.25,31.98 24.25,32.22 24.49,32.46 24.56,32.46 24.73,32.63 24.73,33.43 v1(24.38,33.78) ; R27.2 10.22,50.8 v1(10.86,50.16)
  L3_SIG w0.127: v1(22.21,50) 22.21,45.15 21.5,44.44 21.4,44.44 21.01,44.05 21.01,43.09 20.74,42.82 20.74,38.58 20.94,38.38 20.94,35.22 20.71,34.99 20.71,34.49 20.39,34.17 20.39,31.66 v1(20.46,31.59) ; v1(24.26,36.03) 24.38,35.9 v1(24.38,33.78)
  L4_SIG w0.127: v1(24.26,36.03) 25.8,36.03 26.37,36.6 28.57,36.6 28.99,37.02 28.99,37.33 29.22,37.57 29.79,37.57 v1(30.18,37.17) ; v1(10.86,50.16) 10.99,50.29 12.83,50.29 13.01,50.48 v1(14.61,50.48) 15.26,51.13 21.09,51.13 v1(22.21,50)
AP_GPIO22_SPI0_M_MISO_HDR: length 3.4
  TOP w0.203: R27.1 J15.6
AP_GPIO23_SPI0_M_MOSI: length 55.3
  TOP w0.127: v1(30.98,37.17) 31.38,37.57 U22.D3 ; U23.6 18.26,32.43 18.32,32.36 18.63,32.36 19.91,31.08 v1(19.91,30.7) ; v1(19.72,48.29) 18.53,49.48 U15.5 ; v1(10.16,48.13) R35.2
  L3_SIG w0.127: v1(19.91,30.7) 19.36,31.25 19.36,37.23 19.52,37.39 19.52,39.15 19.23,39.45 19.23,44.34 19.38,44.5 19.38,47.95 v1(19.72,48.29)
  L4_SIG w0.127: v1(31.69,30.15) 31.27,29.73 24.13,29.73 23.69,29.29 22.66,29.29 21.85,30.1 20.52,30.1 v1(19.91,30.7) ; v1(19.72,48.29) 19.61,48.4 15.33,48.4 14.77,47.84 10.46,47.84 v1(10.16,48.13)
  BOTTOM w0.127: v1(30.98,37.17) 31.38,36.77 31.38,35.16 31.28,35.05 31.28,34.71 31.38,34.61 31.38,30.87 31.69,30.56 v1(31.69,30.15)
AP_GPIO23_SPI0_M_MOSI_HDR: length 3.4
  TOP w0.203: J15.8 5.21,48.13 R35.1
AP_GPIO24_SPI0_M_CS0_N: length 52.5
  TOP w0.127: v1(10.79,46.48) 9.97,46.48 R39.2 ; U15.1 14.81,50.98 14.61,51.18 v1(14.61,51.75) ; U22.E4 32.18,38.37 v1(31.78,37.97)
  L3_SIG w0.127: v1(20.43,52.33) 20.72,52.04 20.72,48.4 20.44,48.11 20.44,47.44 20.49,47.39 20.49,43.22 19.98,42.71 19.98,39.94 20.23,39.69 20.23,38.92 20.27,38.88 20.27,38.4 20.49,38.19 20.49,36.12 v1(20.25,35.88) ; v1(10.79,46.48) 9.91,46.48 8.83,47.56 8.83,48.89 v1(10.1,50.16)
  L4_SIG w0.127: v1(10.1,50.16) 11.68,51.75 v1(14.61,51.75) 16,51.75 16.44,52.19 17.76,52.19 17.97,51.98 18.53,51.98 18.88,52.33 v1(20.43,52.33) ; v1(20.25,35.88) 20.8,36.44 22.61,36.44 23.62,35.43 23.75,35.3 24.77,35.3 25.02,35.55 27.63,35.55 28.33,36.25 29.21,36.25 29.74,36.77 30.35,36.77 30.58,37.01 30.58,37.32 30.83,37.57 31.31,37.57 31.53,37.79 31.61,37.79 v1(31.78,37.97)
  BOTTOM w0.127: R159.2 v1(14.61,51.75)
AP_GPIO24_SPI0_M_CS0_N_HDR: length 3.4
  TOP w0.203: J15.10 5.21,45.85 R39.1
AP_GPIO25_SPI0_M_CS1_N: length 90.7
  TOP w0.127: U22.E3 32.18,37.57 v1(31.78,37.17) ; v1(41.27,67.44) 41.3,67.47 Q4.1 ; R43.2 v1(9.33,42.29)
  L3_SIG w0.127: v1(31.78,37.17) 32.19,37.57 32.19,38.93 32.44,39.18 32.75,39.18 32.98,39.41 32.98,39.74 32.88,39.84 32.88,40.2 32.19,40.89 32.19,46.2 31.18,47.21 31.18,49.64 30.3,50.52 30.3,57.25 31.05,58 31.05,58.48 31.32,58.75 31.32,64.74 28.62,67.44 v1(28.45,67.44) ; v1(9.33,42.29) 9.04,42 9.04,37.43 9.68,36.79 9.89,36.79 9.89,36.79 10.43,36.79 11.15,36.07 11.15,34.49 v1(10.73,34.07)
  L4_SIG w0.127: v1(31.78,37.17) 32.19,36.77 32.75,36.77 32.98,36.53 32.98,36.21 32.74,35.97 32.42,35.97 32.19,35.73 32.19,35.42 30.9,34.13 25.71,34.13 25.64,34.19 22.57,34.19 22.42,34.34 20.75,34.34 20.58,34.18 17.72,34.18 16.3,32.75 15.39,32.75 15.16,32.99 15.16,33.31 14.56,33.91 10.89,33.91 v1(10.73,34.07) ; v1(41.27,67.44) 40.64,68.07 29.08,68.07 v1(28.45,67.44)
  BOTTOM w0.127: R209.2 31.94,35.12 32.18,35.36 32.18,36.77 v1(31.78,37.17)
AP_GPIO25_SPI0_M_CS1_N_HDR: length 3.4
  TOP w0.203: R43.1 5.21,43.31 J15.12
AP_GPIO26_SPI0_M_CS2_N: length 79.4
  TOP w0.127: R48.2 v1(13.84,40.51) ; v1(37.72,66.2) 37.72,68.3 38,68.58 38.73,68.58 39.27,69.12 Q5.1 ; v1(27.56,34.92) 27.56,35.1 28.79,36.33 29.35,36.33 U22.B2
  L3_SIG w0.127: v1(20,66.29) 19.56,66.74 16.95,66.74 15.88,65.66 15.88,56.32 14.13,54.58 14.13,48.25 14.11,48.22 14.11,43.41 14.66,42.86 14.66,41.33 v1(13.84,40.51) 13.84,39.18 14.63,38.39 14.63,38.22 14.92,37.93 14.92,35.74 14.87,35.69 14.87,34.79 14.93,34.73 v1(15.24,34.42)
  L4_SIG w0.127: v1(15.24,34.42) 16.27,35.45 20.54,35.45 21.3,36.21 22.52,36.21 23.66,35.07 24.87,35.07 25.01,35.22 27.26,35.22 v1(27.56,34.92) ; v1(37.72,66.2) 34.72,66.2 34.68,66.16 25.46,66.16 25.12,66.51 24.98,66.64 24.85,66.78 24.72,66.91 23.57,66.91 22.58,65.92 20.38,65.92 v1(20,66.29)
  BOTTOM w0.127: v1(27.56,34.92) R212.2
AP_GPIO26_SPI0_M_CS2_N_HDR: length 8
  TOP w0.203: R48.1 11.86,40.06 11.54,40.06 11.2,39.71 6.01,39.71 J15.14
AP_GPIO27_SPI0_M_CS3_N: length 10.7
  TOP w0.127: v1(27.43,35.94) 28.26,36.77 U22.A2 ; v1(28.13,30.92) 28.36,31.16 U33.4
  L3_SIG w0.127: v1(27.43,35.94) 27.95,35.42 27.95,33.47 28.13,33.29 v1(28.13,30.92)
  BOTTOM w0.127: R207.2 25.46,35.37 25.59,35.24 26.73,35.24 v1(27.43,35.94)
AP_GPIO27_SPI0_M_CS3_N_HDR: length 7.7
  TOP w0.203: J15.16 6.01,37.17 11.18,37.17 11.48,37.46 R54.1
AP_GPIO27_SPI0_M_CS3_N_MUX: length 24.7
  TOP w0.127: U23.3 15.99,34.38 15.49,34.87 v1(15.49,35.43) 13.97,36.96 13.72,36.96 R54.2 ; v1(23.65,30.5) 23.68,30.5 25.08,31.9 25.08,32.57 25.4,32.89 U33.1
  L3_SIG w0.127: v1(15.05,30.96) 15.05,31.63 15.16,31.75 15.16,33.31 15.86,34.01 15.86,35.06 v1(15.49,35.43)
  L4_SIG w0.127: v1(23.65,30.5) 23.36,30.78 21.43,30.78 21.08,31.13 21.08,31.85 20.72,32.21 19.38,32.21 18.55,31.38 15.47,31.38 v1(15.05,30.96)
AP_GPIO28: length 20.9
  TOP w0.127: R61.1 40.58,46.29 v1(40.58,45.4) 40.91,45.73 U16.3 ; U22.C2 30.58,36.77 v1(30.18,36.37)
  L3_SIG w0.127: v1(38.86,39.42) 38.86,43.63 40.58,45.35 v1(40.58,45.4)
  L4_SIG w0.127: v1(30.18,36.37) 30.41,36.37 30.81,36.77 31.14,36.77 31.15,36.77 31.38,37.01 31.39,37.02 31.39,37.33 31.62,37.56 31.93,37.56 31.95,37.57 32.18,37.81 32.19,37.82 32.19,39.74 32.42,39.97 38.31,39.97 v1(38.86,39.42)
AP_GPIO_AON0: length 43.1
  TOP w0.127: R105.1 49.91,19.56 v1(50.99,20.64) ; v1(32.59,37.17) 32.98,37.57 U22.F3
  L3_SIG w0.127: v1(32.59,37.17) 33.22,36.54 33.22,34.92 33.34,34.81 33.34,33.38 33.08,33.13 33.08,30.81 33.67,30.22 33.67,25.57 32.88,24.79 v1(32.88,20.38)
  L4_SIG w0.127: v1(50.99,20.64) 50.61,21.02 45.16,21.02 45.13,20.99 38.93,20.99 38.57,21.35 35.69,21.35 34.47,20.13 33.14,20.13 v1(32.88,20.38)
  BOTTOM w0.127: v1(50.99,20.64) 51.05,20.7 R221.1
AP_GPIO_AON0_HDR: length 8.7
  BOTTOM w0.203: 63.5,20.32 60.13,20.32 59.06,21.4 57.91,21.4 57.21,20.7 R221.2
AP_GPIO_AON0_R: length 3.7
  TOP w0.127: R102.1 R105.2 R106.2 48.13,18.28 U29.26
AP_GPIO_AON1: length 97.3
  TOP w0.127: U22.F5 32.98,39.17 v1(32.59,38.77)
  L3_SIG w0.127: v1(60.57,51.37) 60.37,51.16 60.37,43.68 60.24,43.55 60.24,42.94 60.71,42.47 60.71,37.77 v1(60.4,37.46) 60.53,37.33 60.53,33.37 60.4,33.23 60.24,33.07 60.24,31.08 60.26,31.05 60.26,29.83 59.82,29.39 59.82,28.63 60.48,27.97 60.48,26.41 60.1,26.04 v1(60.1,18.02)
  L4_SIG w0.127: v1(60.57,51.37) 60.57,63.27 64.07,66.76 64.07,69.7 v1(65.3,70.93) ; v1(60.4,37.46) 59.89,37.97 57.87,37.97 56.41,36.51 48.3,36.51 46.51,34.72 43.33,34.72 42.8,35.25 42.8,35.26 42.44,35.61 42.43,35.61 42.42,35.62 38.99,35.62 38.65,35.97 34.03,35.97 32.98,37.01 32.98,38.38 v1(32.59,38.77) ; v1(53.78,18.61) 53.99,18.81 59.32,18.81 v1(60.1,18.02)
  BOTTOM w0.127: v1(53.78,18.61) 53.78,18.54 53.85,18.48 R226.1 ; v1(65.3,70.93) 65.61,70.62 U32.6
AP_GPIO_AON1_HDR: length 8.6
  BOTTOM w0.203: 63.5,17.78 62.4,18.88 57.75,18.88 57.34,18.48 R226.2
AP_GPIO_AON2: length 119
  TOP w0.127: U22.F4 32.98,38.37 v1(32.59,37.97)
  L3_SIG w0.127: v1(61.02,49.66) 61.63,49.05 61.63,33.5 60.92,32.79 60.92,31.36 62.01,30.27 62.01,14.64 v1(60.29,12.92) ; v1(32.59,37.97) 33.45,37.11 33.45,35.02 33.57,34.9 33.57,32.93 33.31,32.68 33.31,30.9 33.9,30.32 33.9,16.12 v1(32.38,14.61) ; v1(53.98,16.26) 53.98,15.31 53.34,14.67 v1(53.34,13.78)
  L4_SIG w0.127: v1(53.34,13.78) 53.04,13.48 39.26,13.48 38.45,14.29 37.88,14.29 37.42,13.82 33.17,13.82 v1(32.38,14.61) ; v1(66.83,69.12) 66.83,68.67 61.91,63.75 61.91,50.55 v1(61.02,49.66)
  BOTTOM w0.127: R235.1 v1(53.98,16.26) ; v1(60.29,12.92) 59.55,13.65 55.25,13.65 54.97,13.37 54.44,13.37 54.2,13.61 54.2,13.61 54.04,13.78 v1(53.34,13.78) ; U32.1 66.69,69.26 v1(66.83,69.12)
AP_GPIO_AON2_HDR: length 8.4
  BOTTOM w0.203: R235.2 59.56,16.26 60.58,15.24 63.5,15.24
AP_GPIO_AON3: length 82.9
  TOP w0.127: U22.F2 32.98,36.77 v1(32.59,36.37)
  L3_SIG w0.127: v1(15.56,33.15) 16.09,33.68 16.09,39.21 15.23,40.07 15.23,43.05 15.25,43.08 15.25,44.01 15.23,44.04 15.23,46.6 v1(15.62,46.99) ; v1(32.59,36.37) 32.98,35.98 32.98,35.28 32.31,34.6 32.31,33.33 32.31,33.33 32.31,33.28 32.57,33.02 32.57,30.38 32.57,30.38 32.57,29.86 32.57,29.86 32.57,25.23 32.28,24.94 32.28,20.83 31.44,19.99 31.44,18.37 32.27,17.54 32.27,15.26 31.99,14.98 31.99,14.44 32.22,14.21 34.27,14.21 v1(34.91,14.85)
  L4_SIG w0.127: v1(32.59,36.37) 32.34,36.37 31.94,35.97 31.62,35.97 31.39,35.73 31.39,35.42 30.33,34.35 25.8,34.35 25.73,34.42 22.66,34.42 21.89,35.19 21.18,35.19 20.39,34.4 16.82,34.4 v1(15.56,33.15) ; v1(34.91,14.85) 35.35,14.85 35.55,15.05 38.4,15.05 39.68,13.77 52.5,13.77 53.21,14.48 v1(53.78,14.48)
  BOTTOM w0.127: R240.1 v1(53.78,14.48) ; R183.1 v1(15.62,46.99)
AP_GPIO_AON3_HDR: length 8.7
  BOTTOM w0.203: 63.5,12.7 62.1,14.1 57.4,14.1 57.02,14.48 R240.2
AP_GPIO_AON4: length 99.6
  TOP w0.127: v1(32.59,35.57) 32.98,35.97 U22.F1
  L3_SIG w0.127: v1(39.76,65.99) 39.76,58.04 42.75,55.06 42.75,50.9 44.84,48.8 44.84,37.11 42.33,34.59 40.35,34.59 v1(40.1,34.84) ; v1(32.59,35.57) 32.59,35.21 32.08,34.7 32.08,33.94 32.08,33.43 32.08,33.24 32.08,33.23 32.08,33.18 32.34,32.92 32.34,30.48 32.34,30.47 32.34,29.77 32.34,29.76 32.34,26.22 32.29,26.17 32.29,25.28 32.05,25.03 32.05,22.78 30.47,21.2 30.47,18.44 31.45,17.46 31.45,14.13 34.48,11.1 v1(34.48,9.92) ; v1(53.91,12.07) 53.4,11.56 v1(53.4,10.99)
  L4_SIG w0.127: v1(34.48,9.92) 35.29,9.92 35.37,9.84 46.23,9.84 46.4,10.01 52.43,10.01 v1(53.4,10.99) ; v1(32.59,35.57) 33.68,35.57 33.68,35.57 34.01,35.57 34.01,35.57 34.79,35.57 35.24,35.11 38.52,35.11 38.73,35.32 39.27,35.32 39.74,34.85 40.11,34.85 40.11,34.84 v1(40.1,34.84)
  BOTTOM w0.127: R136.2 40.58,68.58 40.58,67.63 40.58,67.63 40.58,66.8 v1(39.76,65.99) 39.75,65.97 C105.1 ; R247.1 v1(53.91,12.07)
AP_GPIO_AON4_HDR: length 8.8
  BOTTOM w0.203: J14.43 61.02,10.16 59.56,11.62 56.64,11.62 56.2,12.07 R247.2
AP_GPIO_AON5: length 90.6
  TOP w0.127: R195.1 15.49,15.3 v1(16.07,15.88) ; U22.E6 32.18,39.97 v1(31.78,39.57)
  L3_SIG w0.127: v1(16.26,8.06) 16.26,8.53 16.91,9.19 18.01,9.19 18.73,9.91 18.73,10.92 17.91,11.75 17.21,11.75 16.07,12.89 v1(16.07,15.88) 16.45,16.26 16.45,18.8 v1(17.4,19.75) ; v1(23.75,20.07) 24.52,20.84 24.52,21.96 23.74,22.74 23.74,24.46 23,25.2 23,27.67 24.77,29.44 24.77,30.93 26.59,32.75 26.59,35.58 26.58,35.59 26.58,36.3 26.9,36.62 26.9,37.06 27.73,37.9 27.73,38.32 28.57,39.16 31.3,39.16 31.7,39.57 v1(31.78,39.57)
  L4_SIG w0.127: v1(23.75,20.07) 23.73,20.08 17.73,20.08 v1(17.4,19.75) ; v1(50.1,8.85) 49.11,8.85 48.31,8.04 43.01,8.04 42.61,8.45 36.89,8.45 36.57,8.76 33.91,8.76 32.37,7.23 18.85,7.23 18.54,6.92 16.83,6.92 16.26,7.49 v1(16.26,8.06)
  BOTTOM w0.127: R255.1 53.63,8.55 50.4,8.55 v1(50.1,8.85)
AP_GPIO_AON5_HDR: length 8.8
  BOTTOM w0.203: J14.45 61.02,7.62 59.81,8.83 57.65,8.83 56.96,9.52 R255.2
AP_GPIO_SS0_ADC8_UART1_CTS_N: length 16.1
  TOP w0.127: v1(32.58,44.37) 32.98,43.97 U22.F11 ; v1(22.99,42.72) U20.9
  L4_SIG w0.127: v1(32.58,44.37) 32.58,44.29 32.19,43.89 32.19,43.42 31.93,43.16 31.62,43.16 31.39,42.93 31.39,42.62 31.15,42.37 30.83,42.37 30.58,42.12 30.58,41.8 30.35,41.57 27.92,41.57 26.34,43.16 23.42,43.16 v1(22.99,42.72)
  BOTTOM w0.127: v1(32.58,44.37) 33.15,44.93 33.15,46.29 R174.2
AP_GPIO_SS1_ADC9_UART1_RTS_N: length 19.2
  TOP w0.127: v1(20.07,46.99) 21.06,46 21.06,45.81 21.42,45.44 21.61,45.44 21.79,45.27 U20.12 ; U22.F12 32.98,45.23 v1(32.6,45.61)
  L4_SIG w0.127: v1(20.07,46.99) 20.38,46.99 20.78,46.6 23.95,46.6 24.23,46.88 31.38,46.88 32.6,45.65 v1(32.6,45.61)
  BOTTOM w0.127: R175.2 32.6,46.58 v1(32.6,45.61)
AP_GPIO_SS2_ADC10: length 88
  TOP w0.127: U22.G9 v1(34.18,42.77) ; R34.2 v1(54.74,48.26)
  L3_SIG w0.127: v1(57.2,48.92) 57.07,48.8 57.07,42.93 56.87,42.72 56.87,41.78 v1(57.04,41.62) ; v1(13.21,43.07) 13.21,41.24 12.99,41.03 12.99,41.01 12.89,40.91 12.89,39.25 12.99,39.14 13.04,39.09 13.04,38.85 13.05,38.84 13.05,37.91 13.06,37.9 13.06,37.14 13.06,37.11 13.22,36.94 13.22,20.43 v1(14.73,18.92)
  L4_SIG w0.127: v1(54.74,48.26) 56.54,48.26 v1(57.2,48.92) ; v1(13.21,43.07) 14.47,43.07 15.05,42.48 16.64,42.48 17.27,41.85 23.01,41.85 23.63,42.46 23.63,42.69 23.86,42.93 26.12,42.93 27.83,41.22 27.83,41.14 28.19,40.77 30.35,40.77 30.58,41 30.58,41.32 30.83,41.57 31.15,41.57 31.38,41.8 31.38,42.12 31.63,42.37 33.79,42.37 v1(34.18,42.77) 34.18,42.62 34.58,42.22 34.58,41.82 34.87,41.52 36.74,41.52 37.6,40.66 38.82,40.66 41.27,38.21 46.92,38.21 47.74,39.03 54.45,39.03 v1(57.04,41.62)
  BOTTOM w0.127: R225.1 v1(14.73,18.92)
AP_GPIO_SS2_ADC10_HDR: length 10.7
  TOP w0.203: J14.14 64.79,49.51 61.76,49.51 60.6,48.35 56.48,48.35 R34.1
AP_GPIO_SS3_ADC11: length 82.5
  TOP w0.127: R40.2 54.74,45.21 54.74,45.21 v1(54.8,45.21) ; U22.G10 v1(34.18,43.57)
  L3_SIG w0.127: v1(12.9,46.04) 12.9,43.76 12.67,43.54 12.53,43.4 12.53,41.2 12.43,41.1 12.43,39.06 12.53,38.96 12.53,38.71 12.59,38.65 12.59,37.72 12.6,37.71 12.6,36.95 12.6,36.95 12.6,36.92 12.76,36.75 12.76,19.05 v1(14.67,17.14) ; v1(34.18,43.57) 34.59,43.97 34.59,45.02 34.62,45.05 34.62,45.38 34.16,45.83 34.16,47.56 v1(33.46,48.26)
  L4_SIG w0.127: v1(54.8,45.21) 54.15,45.86 51.24,45.86 50.84,45.45 50.51,45.45 50,45.96 47,45.96 46.61,46.35 43.8,46.35 42.52,47.64 35.99,47.64 35.37,48.26 v1(33.46,48.26) 32.69,47.48 26.59,47.48 26.51,47.41 22.45,47.41 22.17,47.69 21.28,47.69 20.99,47.41 20.67,47.41 20.46,47.61 19.68,47.61 19.21,47.15 19.21,46.81 18.8,46.4 13.26,46.4 v1(12.9,46.04)
  BOTTOM w0.127: R234.1 v1(14.67,17.14)
AP_GPIO_SS3_ADC11_HDR: length 10.9
  TOP w0.203: R40.1 57.15,45.21 57.66,45.72 59.82,45.72 61.09,46.98 64.78,46.98 J14.16
AP_GPIO_SS4_ADC12: length 42.4
  TOP w0.127: U22.G11 v1(34.18,44.37) ; v1(53.98,43.18) 54.48,42.67 54.99,42.67 R45.2
  L3_SIG w0.127: v1(34.18,44.37) 33.91,44.64 33.91,44.97 33.83,45.05 33.83,45.38 33.91,45.45 33.91,46.35 33.02,47.24 33.02,51.5 v1(34.16,52.64)
  L4_SIG w0.127: v1(34.16,52.64) 33.46,53.34 29.97,53.34 v1(28.58,51.94) ; v1(34.18,44.37) 34.26,44.37 34.66,43.97 35.15,43.97 36.43,45.26 36.43,45.33 37.56,46.46 41.1,46.46 42.35,45.21 46.67,45.21 47.19,44.69 47.87,44.69 48.12,44.95 49.99,44.95 51.34,43.6 53.56,43.6 v1(53.98,43.18)
  BOTTOM w0.127: R156.2 v1(28.58,51.94) 28,51.94 27.88,51.82
AP_GPIO_SS4_ADC12_HDR: length 11.1
  TOP w0.203: J14.18 64.77,44.45 60.73,44.45 59.52,43.24 57.98,43.24 56.9,42.16 R45.1
AP_GPIO_SS5_ADC13: length 70.6
  TOP w0.127: R53.2 v1(54.74,38.1) ; v1(34.67,46.04) 34.23,46.04 33.78,45.59 U22.G12
  L3_SIG w0.127: v1(32.26,58.29) 32.48,58.07 32.48,57.56 33.72,56.32 33.72,53.91 35.12,52.51 35.12,50.86 35.26,50.72 35.26,47.8 34.47,47.02 34.47,46.24 v1(34.67,46.04) ; v1(51.97,45.08) 51.97,43.58 53.17,42.38 53.92,42.38 54.17,42.13 54.17,41.65 55,40.81 55,39.34 54.74,39.08 v1(54.74,38.1)
  L4_SIG w0.127: v1(32.26,58.29) 31.81,58.74 31.31,58.74 30.99,58.42 28.32,58.42 27.18,57.28 18.22,57.28 16.7,55.75 15.88,55.75 13.72,53.59 v1(11.37,53.59) ; v1(51.97,45.08) 50.55,45.08 49.98,45.66 46.93,45.66 46.69,45.9 42.34,45.9 41.15,47.09 34.71,47.09 34.48,46.86 34.48,46.23 v1(34.67,46.04)
  BOTTOM w0.127: v1(11.37,53.59) 10.22,54.74 R127.1
AP_GPIO_SS5_ADC13_HDR: length 10.7
  TOP w0.203: J14.20 64.77,39.37 62.77,39.37 62.02,38.62 56.91,38.62 R53.1
AP_GPIO_SS6_ADC14: length 104.4
  TOP w0.127: v1(54.74,35.94) 54.86,36.07 R59.2 ; U22.K10 v1(36.58,43.57)
  L3_SIG w0.127: v1(54.74,35.94) 55.48,36.68 55.48,43.19 54.99,43.68 53.58,43.68 v1(53.09,43.18) ; v1(59.82,15.37) 59.68,15.5 59.68,18.38 59.72,18.41 59.72,26.95 59.46,27.2 59.46,28.33 59.36,28.44 59.36,29.58 59.8,30.02 59.8,30.86 59.78,30.89 59.78,33.26 59.8,33.29 59.8,35.83 v1(59.5,36.13)
  L4_SIG w0.127: v1(59.82,15.37) 58.74,16.44 55.19,16.44 54.82,16.81 53.51,16.81 52.95,16.24 41.34,16.24 39.77,17.82 37.95,17.82 37.78,17.99 35.08,17.99 34.81,17.72 28.57,17.72 27.49,16.63 15.87,16.63 v1(14.61,15.37) ; v1(59.5,36.13) 58.99,36.13 58.8,35.94 v1(54.74,35.94) ; v1(53.09,43.18) 51.37,43.18 49.83,44.72 49.16,44.72 48.35,43.9 45.31,43.9 45.07,44.14 41.22,44.14 40.91,44.46 39.41,44.46 38.92,43.97 36.99,43.97 v1(36.58,43.57)
  BOTTOM w0.127: R238.1 v1(14.61,15.37)
AP_GPIO_SS6_ADC14_HDR: length 10.9
  TOP w0.203: R59.1 56.83,35.62 60.07,35.62 61.28,36.83 64.77,36.83 66.04,38.1
AP_GPIO_SS7_ADC15: length 86.9
  TOP w0.102: U22.K9 v1(36.58,42.77)
  TOP w0.127: R65.2 v1(54.74,34.04)
  L3_SIG w0.127: v1(36.58,42.77) 36.67,42.77 37.07,43.16 37.67,43.16 37.91,42.93 37.91,41.45 37.79,41.33 37.79,39.74 39.69,37.85 39.69,29.73 37.79,27.82 37.79,15.77 35.67,13.65 35.67,11.82 v1(34.93,11.08) ; v1(54.74,34.04) 54.29,34.48 54.29,35.43 54.03,35.7 54.03,36.5 54.27,36.74 54.27,38.93 54.77,39.44 54.77,40.5 53.69,41.59 v1(53.69,41.81)
  L4_SIG w0.127: v1(53.69,41.81) 52.93,41.81 51.99,40.88 40.29,40.88 38.81,42.36 37.07,42.36 36.66,42.77 v1(36.58,42.77) ; v1(34.93,11.08) 33.49,11.08 33.07,10.66 28.56,10.66 27.56,11.66 17.12,11.66 16.37,10.91 15.51,10.91 v1(14.61,11.81)
  BOTTOM w0.127: R248.1 v1(14.61,11.81)
AP_GPIO_SS7_ADC15_HDR: length 10.8
  TOP w0.203: 66.04,35.56 64.95,34.47 61.01,34.47 60.01,33.46 56.96,33.46 R65.1
AP_GPIO_SS8_ADC16_UART1_TXD: length 27.7
  TOP w0.127: U22.H11 v1(34.98,44.37) ; U20.4 18.61,45.92 v1(18.67,45.97)
  L4_SIG w0.127: v1(34.98,44.37) 35.51,44.89 35.51,45.44 35.28,45.67 34.94,45.67 34.91,45.64 34.06,45.64 32.6,47.1 22.43,47.1 22.15,47.38 21.29,47.38 21.09,47.18 20.57,47.18 20.37,47.38 19.9,47.38 19.51,46.99 19.51,46.79 18.7,45.97 v1(18.67,45.97)
  BOTTOM w0.127: v1(34.98,44.37) 35.69,45.07 35.69,47.18 36.2,47.69 36.2,49.15 36.13,49.21 R172.2
AP_GPIO_SS9_ADC17_UART1_RXD: length 24.2
  TOP w0.127: U22.H12 34.23,45.13 v1(34.23,45.21) ; U20.7 18.64,43.97 v1(18.67,43.94)
  L4_SIG w0.127: v1(18.67,43.94) 19,43.94 19.63,44.56 23.21,44.56 24.61,45.96 29.15,45.96 29.79,45.32 29.79,45 30.03,44.76 30.35,44.76 30.58,44.53 30.58,44.22 30.82,43.97 31.95,43.97 32.19,44.22 32.19,44.53 32.87,45.21 v1(34.23,45.21)
  BOTTOM w0.127: v1(34.23,45.21) 34.54,45.53 34.72,45.53 35.43,46.24 35.43,47.56 35.75,47.88 R173.2
AP_GPIO_SS10_PWM0: length 55.4
  TOP w0.127: v1(54.67,30.23) 54.67,30.61 55.05,30.99 R70.1 ; v1(30.98,36.37) 31.38,36.77 U22.D2 ; U28.11 24.81,24.17 v1(25.15,24.51)
  L3_SIG w0.127: v1(54.67,30.23) 54.67,28.61 54.2,28.14 54.2,25.77 51.76,23.32 51.76,22.42 v1(51.31,21.97) ; v1(30.98,36.37) 30.59,35.97 30.59,34.77 30.43,34.61 30.43,30.71 27.57,27.85 27.57,27 26.72,26.14 26.72,25.78 25.96,25.02 25.65,25.02 v1(25.15,24.51)
  L4_SIG w0.127: v1(51.31,21.97) 51.31,22.03 50.58,22.76 50.58,22.76 50.53,22.81 45.33,22.81 45.14,22.62 39.87,22.62 39.52,22.97 38.97,22.97 38.61,22.62 34.66,22.62 33.84,23.44 26.22,23.44 v1(25.15,24.51)
AP_GPIO_SS10_PWM0_HDR: length 8
  TOP w0.203: 63.5,33.02 62.56,32.08 60.15,32.08 59.05,30.99 R70.2
AP_GPIO_SS11_PWM1: length 45
  TOP w0.127: v1(53.67,27.94) 54.06,27.94 55.08,28.96 R74.1 ; v1(29.39,35.57) 29.78,35.97 U22.B1 ; U28.5 25.46,27.61 v1(25.15,27.3)
  L3_SIG w0.127: v1(25.15,27.3) 25.24,27.3 26.06,28.13 26.54,28.13 28.98,30.57 28.98,34.45 29.39,34.86 v1(29.39,35.57)
  L4_SIG w0.127: v1(53.67,27.94) 52.03,27.94 51.94,27.85 50.7,27.85 49.99,28.56 46.21,28.56 45.63,27.98 39.32,27.98 38.4,28.91 35.1,28.91 34.89,28.69 26.53,28.69 v1(25.15,27.3)
AP_GPIO_SS11_PWM1_HDR: length 8.1
  TOP w0.203: R74.2 56.9,28.96 57.32,28.54 61.56,28.54 J14.27
AP_GPIO_SS12_PWM2: length 48.7
  TOP w0.127: U22.E2 32.18,36.77 v1(31.79,36.37) ; U28.14 26.76,24.89 27.77,25.91 v1(28.19,25.91) ; R76.1 v1(54.74,27.94)
  L3_SIG w0.127: v1(31.79,36.37) 31.39,35.97 31.39,35.47 31.38,35.46 31.38,35.41 31.15,35.18 31.1,35.18 31.06,35.14 31.06,34.62 31.06,34.62 31.06,30.74 30.89,30.56 30.89,30.52 28.82,28.45 28.82,26.53 v1(28.19,25.91)
  L4_SIG w0.127: v1(54.74,27.94) 54.99,27.69 55.09,27.69 55.29,27.48 55.29,27.48 55.42,27.35 55.42,25.69 55.09,25.35 54.31,25.35 54.18,25.48 53.67,25.99 53.67,26.06 53.43,26.3 51.79,26.3 51.76,26.33 35.94,26.33 34.63,27.64 32.5,27.64 31.43,26.57 28.85,26.57 v1(28.19,25.91)
AP_GPIO_SS12_PWM2_HDR: length 7.2
  TOP w0.203: R76.2 56.45,28 63.44,28 J14.29
AP_GPIO_SS13_PWM3: length 42.8
  TOP w0.127: v1(27.18,27.3) 27.41,27.53 U28.2 ; U22.C1 30.58,35.97 v1(30.19,35.57) ; v1(54.74,26.04) 54.74,25.65 R82.1
  L3_SIG w0.127: v1(27.18,27.3) 27.18,27.78 30.2,30.8 30.2,34.76 30.19,34.77 v1(30.19,35.57)
  L4_SIG w0.127: v1(27.18,27.3) 28.33,28.46 34.56,28.46 34.7,28.32 34.92,28.32 35.37,27.86 39.12,27.86 39.23,27.75 45.83,27.75 46.41,28.33 49.89,28.33 50.64,27.58 53.31,27.58 54.74,26.15 v1(54.74,26.04)
AP_GPIO_SS13_PWM3_HDR: length 7.3
  TOP w0.203: R82.2 62.99,24.89 J14.31
AP_GPIO_SS14_PLT_CLK_0: length 58.7
  TOP w0.127: U22.D1 31.38,35.97 v1(30.99,35.57) ; R49.1 54.34,40.13 v1(54.32,40.16) ; U25.11 30.9,24.17 v1(31.24,24.51)
  L3_SIG w0.127: v1(51.12,23.24) 51.12,27.18 52.64,28.7 52.64,38.03 54.32,39.71 v1(54.32,40.16) ; v1(27.18,25.91) 27.18,26.14 27.8,26.76 27.8,27.76 30.66,30.62 30.66,30.65 30.82,30.81 30.82,35.4 v1(30.99,35.57)
  L4_SIG w0.127: v1(27.18,25.91) 27.18,25.39 27.36,25.21 29.53,25.21 29.77,24.97 30.79,24.97 v1(31.24,24.51) 31.64,24.9 33.44,24.9 33.9,24.45 33.9,24.35 34.13,24.12 40.43,24.12 40.47,24.16 41.72,24.16 41.83,24.04 50.32,24.04 v1(51.12,23.24)
AP_GPIO_SS14_PLT_CLK_0_HDR: length 7.3
  TOP w0.203: R49.2 57.09,40.13 57.6,40.64 J14.19
AP_GPIO_SS15_PLT_CLK_1: length 62
  TOP w0.127: U25.14 32.85,25.49 v1(33.27,25.91) ; R55.1 55.5,37.55 55.54,37.59 56.95,37.59 57.12,37.77 v1(57.12,38.13) ; U22.E1 32.18,35.97 v1(31.79,35.57)
  L3_SIG w0.127: v1(29.21,25.91) 29.21,26.29 29.68,26.76 29.68,28.99 31.11,30.43 31.11,30.46 31.29,30.64 31.29,34.72 31.29,34.72 31.29,34.99 31.57,35.28 31.58,35.28 31.79,35.49 v1(31.79,35.57) ; v1(57.12,38.13) 56.76,37.76 56.76,25.86 57.83,24.79 57.83,24.39 57.03,23.59 v1(57.03,23.3)
  L4_SIG w0.127: v1(57.03,23.3) 53.34,23.3 52.15,24.5 42.02,24.5 41.91,24.61 40.28,24.61 40.24,24.57 35.9,24.57 35.19,25.29 33.97,25.29 33.79,25.46 33.72,25.46 v1(33.27,25.91) 32.82,25.45 32.16,25.45 32.12,25.41 31.61,25.41 31.57,25.45 29.98,25.45 29.52,25.91 v1(29.21,25.91)
AP_GPIO_SS15_PLT_CLK_1_HDR: length 7.5
  TOP w0.203: 63.5,38.1 57.99,38.1 56.98,37.08 R55.2
AP_I2C0_SCL: length 139.2
  TOP w0.127: v1(16.5,54.26) 15.39,53.15 12.51,53.15 12.31,52.95 U12.6 ; R265.1 17.59,59.05 v1(17.53,59.12) ; U22.C12 v1(30.18,45.17)
  L3_SIG w0.127: v1(30.18,45.17) 30.18,46.27 29.02,47.43 29.02,50.55 29.08,50.61 29.08,52.69 28.87,52.9 v1(28.87,57.57) ; v1(15.62,20.26) 16.14,20.78 16.14,25.64 16.12,25.67 16.12,30.67 16.55,31.1 16.55,39.73 16.47,39.81 16.47,43.26 16.24,43.49 16.24,50.97 15.23,51.98 15.23,52.98 v1(16.5,54.26) ; v1(42.86,31.37) 42.94,31.45 42.94,33.07 42.89,33.12 42.89,33.68 43.31,34.1 45.21,34.1 45.97,34.86 45.97,35.88 46.8,36.7 46.8,42.67 45.27,44.2 45.27,48.2 45.92,48.85 45.92,57.59 v1(46.38,58.04)
  L4_SIG w0.127: v1(23.37,19.18) 22.91,18.72 20.65,18.72 20.13,19.24 16.64,19.24 v1(15.62,20.26) ; v1(46.38,58.04) 46.01,57.67 36.32,57.67 35.41,56.76 31.24,56.76 30.87,57.12 30.87,57.44 30.51,57.81 29.11,57.81 v1(28.87,57.57) 28.87,57.49 27.92,56.54 25.65,56.54 25.62,56.58 22.61,56.58 20.89,54.86 19.62,54.86 19.05,54.29 18.16,54.29 17.4,53.53 16.83,53.53 16.5,53.85 v1(16.5,54.26)
  BOTTOM w0.127: R230.2 23.37,18.86 v1(23.37,19.18) ; v1(17.53,59.12) 17.97,58.67 17.97,56.64 16.5,55.17 v1(16.5,54.26) 16.5,53.65 R153.2 ; v1(15.62,20.26) 15.18,20.7 14.86,20.7 R220.1 ; R198.1 44.45,31.56 44.26,31.37 v1(42.86,31.37)
AP_I2C0_SCL_AMBIENT: length 4.7
  TOP w0.127: U10.5 20.07,55.37 19.18,56.26 19.18,57.21 19.69,57.72 19.69,58.55 19.18,59.05
AP_I2C0_SCL_BLE: length 3.6
  TOP w0.127: v1(22.42,19.18) 22.41,19.17 U30.24
  BOTTOM w0.127: R230.1 22.42,18.92 v1(22.42,19.18)
AP_I2C0_SCL_HDR: length 12.1
  BOTTOM w0.203: R220.2 12,21.59 10.73,20.32 8.64,20.32 7.37,19.05 3.81,19.05 J15.31
AP_I2C0_SCL_TEMP: length 2.4
  TOP w0.127: v1(44.45,33.59) 44.77,33.27 U21.1
  BOTTOM w0.127: R198.2 v1(44.45,33.59)
AP_I2C0_SDA: length 140.3
  TOP w0.127: U12.5 15.46,52.29 v1(15.62,52.45) ; v1(17.53,58.23) 17.59,58.17 R264.1 ; U22.B12 v1(29.38,45.17)
  L3_SIG w0.127: v1(15.56,18.92) 15.9,19.27 15.9,19.41 16.78,20.28 16.78,24.96 16.75,24.98 16.75,25.54 16.35,25.95 16.35,30.51 16.78,30.94 16.78,39.82 16.7,39.9 16.7,43.98 16.47,44.2 16.47,51.6 v1(15.62,52.45) ; v1(47.37,58.05) 46.15,56.83 46.15,48.76 45.58,48.18 45.58,44.51 47.12,42.98 47.12,36.64 46.23,35.75 46.23,34.35 v1(45.47,33.59) ; v1(28.07,57.53) 28.3,57.3 28.3,55.03 27.75,54.49 27.75,52.35 27.76,52.34 27.76,47.42 29.38,45.8 v1(29.38,45.17)
  L4_SIG w0.127: v1(47.37,58.05) 46.91,58.51 46.17,58.51 45.55,57.9 35.31,57.9 35.22,57.81 31.07,57.81 30.7,58.18 28.71,58.18 v1(28.07,57.53) 27.3,56.77 25.78,56.77 25.53,57.02 18.34,57.02 16.81,55.5 16.38,55.5 15.62,54.74 v1(15.62,52.45) ; v1(26.99,19.18) 25.08,17.27 23.75,17.27 23.33,16.86 16.29,16.86 15.56,17.59 v1(15.56,18.92)
  BOTTOM w0.127: R196.1 v1(45.47,33.59) ; R227.2 v1(26.99,19.18) ; v1(15.56,18.92) 14.67,19.81 R223.1 ; v1(17.53,58.23) 16.95,57.66 16.95,56.39 16.07,55.5 16.07,54.04 15.62,53.59 v1(15.62,52.45) 16.19,52.45 R157.2
AP_I2C0_SDA_AMBIENT: length 4.5
  TOP w0.127: 19.18,58.17 19.18,57.72 18.8,57.34 18.8,56.26 19.56,55.5 19.56,54.99 19.83,54.72 U10.6
AP_I2C0_SDA_BLE: length 2.2
  TOP w0.127: v1(27.94,19.18) 28.01,19.11 U30.16
  BOTTOM w0.127: v1(27.94,19.18) 27.94,18.48 R227.1
AP_I2C0_SDA_HDR: length 13.1
  BOTTOM w0.203: R223.2 12.07,19.81 11.35,19.1 9.38,19.1 8.76,18.48 8.76,17.27 8,16.51 3.81,16.51 J15.33
AP_I2C0_SDA_TEMP: length 2
  TOP w0.254: v1(45.4,31.29) 44.81,31.29 44.77,31.25 U21.6
  BOTTOM w0.127: v1(45.4,31.29) 45.4,31.25 45.47,31.32 R196.2
AP_I2C0_SS_SCL: length 52.5
  TOP w0.127: U22.B11 v1(29.38,44.37)
  L3_SIG w0.127: v1(12.95,46.86) 13.29,46.53 13.29,43.83 12.76,43.31 12.76,41.11 12.66,41.01 12.66,39.15 12.76,39.05 12.81,39 12.81,38.75 12.82,38.75 12.82,37.81 12.83,37.81 12.83,37.04 12.83,37.04 12.83,37.01 12.99,36.85 12.99,19.71 v1(14.67,18.03)
  L4_SIG w0.127: v1(12.95,46.86) 13.63,47.54 19,47.54 19.3,47.85 20.32,47.85 20.67,48.19 20.99,48.19 21.08,48.1 23.49,48.1 23.78,48.4 24.82,48.4 25.07,48.15 25.72,48.15 26,47.87 26.33,47.87 26.72,48.26 v1(27.05,48.26)
  BOTTOM w0.127: R231.1 v1(14.67,18.03) ; v1(29.38,44.37) 28.98,44.77 28.98,45.32 28.39,45.92 27.23,45.92 26.48,46.67 R181.2 26.99,47.18 26.99,48.2 v1(27.05,48.26)
AP_I2C0_SS_SCL_HDR: length 12.8
  BOTTOM w0.203: J15.35 3.88,14.04 7.17,14.04 9.64,16.51 10.92,16.51 12.45,18.03 R231.2
AP_I2C0_SS_SDA: length 52.9
  TOP w0.127: U22.A11 v1(28.58,44.37)
  L3_SIG w0.127: v1(11.18,44.07) 12.08,43.17 12.08,41.39 11.97,41.29 11.97,38.87 12.08,38.77 12.08,38.52 12.13,38.46 12.13,37.53 12.14,37.52 12.14,36.76 12.14,36.76 12.14,36.73 12.31,36.56 12.31,16.78 v1(14.61,14.48)
  L4_SIG w0.127: v1(28.58,44.37) 26.65,44.37 26.3,44.72 25.69,44.72 25.14,44.17 22.29,44.17 22.12,44.34 21.08,44.34 20.47,43.73 20.47,43.66 20.06,43.25 19.27,43.25 18.97,43.55 17.79,43.55 17.1,44.23 13.3,44.23 12.63,43.56 11.68,43.56 v1(11.18,44.07)
  BOTTOM w0.127: v1(28.58,44.37) 27.62,45.33 R185.2 ; R241.1 v1(14.61,14.48)
